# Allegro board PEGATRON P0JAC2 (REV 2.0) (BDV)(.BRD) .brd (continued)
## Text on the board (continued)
User.8: list("[Spacing] SOLDERMASK_BOTTOM" "66.Sym Soldermask to Pad Soldermask" "6.7 MIL [SOLDERMASK_SPACING]" "0 MIL" "6.70 MIL" "DRC ERROR CLASS/SOLDERMASK_BOTTOM" "[ThruPin] Dummy (<uTiL>cId4362<uTiL>.1) (-144.19 4584.63)" "[Shape] Package Geometry/Soldermask_Bottom ((-262.3 4419.29) (-0.49 4677.16))" list(-144.190000 4665.250000) nil)@@@list("bobo_dong" "2014/01/13 20:53:31" nil "S0DCOA89102" "g1t-p0jac.11")@@@list("doris_chen" "2014/01/16 14:59:33" nil "JULIA_YU-PC1" "g1t-p0jac_byt-t.13-chk") | list("[Spacing] SOLDERMASK_BOTTOM" "14.Pad Soldermask to Pad Soldermask" "6.7 MIL [SOLDERMASK_SPACING]" "0 MIL" "6.70 MIL" "DRC ERROR CLASS/SOLDERMASK_BOTTOM" "[SmdPin] MCSI_2_CLK_DP_CON (<uTiL>cId875<uTiL>.3) (130.9 3857.59)" "[SmdPin] MCSI_2_CLK_DP_CON (<uTiL>cId2109<uTiL>.4) (128.93 3855.62)" list(128.930000 3855.620000) nil)@@@list("bobo_dong" "2014/01/13 20:52:34" nil "S0DCOA89102" "g1t-p0jac.11")@@@list("doris_chen" "2014/01/16 14:59:02" nil "JULIA_YU-PC1" "g1t-p0jac_byt-t.13-chk") | list("[Spacing] SOLDERMASK_BOTTOM" "12.Pad Soldermask to Pad Soldermask" "6.7 MIL [SOLDERMASK_SPACING]" "0 MIL" "6.70 MIL" "DRC ERROR CLASS/SOLDERMASK_BOTTOM" "[SmdPin] MCSI_2_CLK_DP (<uTiL>cId875<uTiL>.4) (130.9 3808.37)" "[SmdPin] MCSI_2_CLK_DP (<uTiL>cId2109<uTiL>.3) (128.93 3810.34)" list(128.930000 3810.340000) nil)@@@list("bobo_dong" "2014/01/13 20:52:33" nil "S0DCOA89102" "g1t-p0jac.11")@@@list("doris_chen" "2014/01/16 14:59:01" nil "JULIA_YU-PC1" "g1t-p0jac_byt-t.13-chk") | list("[Spacing] SOLDERMASK_BOTTOM" "13.Pad Soldermask to Pad Soldermask" "6.7 MIL [SOLDERMASK_SPACING]" "0 MIL" "6.70 MIL" "DRC ERROR CLASS/SOLDERMASK_BOTTOM" "[SmdPin] MCSI_2_CLK_DN_CON (<uTiL>cId875<uTiL>.2) (152.56 3857.59)" "[SmdPin] MCSI_2_CLK_DN_CON (<uTiL>cId2109<uTiL>.2) (154.53 3855.62)" list(154.530000 3855.620000) nil)@@@list("bobo_dong" "2014/01/13 20:52:32" nil "S0DCOA89102" "g1t-p0jac.11")@@@list("doris_chen" "2014/01/16 14:59:01" nil "JULIA_YU-PC1" "g1t-p0jac_byt-t.13-chk") | list("[Spacing] SOLDERMASK_BOTTOM" "11.Pad Soldermask to Pad Soldermask" "6.7 MIL [SOLDERMASK_SPACING]" "0 MIL" "6.70 MIL" "DRC ERROR CLASS/SOLDERMASK_BOTTOM" "[SmdPin] MCSI_2_CLK_DN (<uTiL>cId875<uTiL>.1) (152.56 3808.37)" "[SmdPin] MCSI_2_CLK_DN (<uTiL>cId2109<uTiL>.1) (154.53 3810.34)" list(154.530000 3810.340000) nil)@@@list("bobo_dong" "2014/01/13 20:52:31" nil "S0DCOA89102" "g1t-p0jac.11")@@@list("doris_chen" "2014/01/16 14:59:00" nil "JULIA_YU-PC1" "g1t-p0jac_byt-t.13-chk") | list("[Spacing] SOLDERMASK_BOTTOM" "17.Pad Soldermask to Pad Soldermask" "6.7 MIL [SOLDERMASK_SPACING]" "0 MIL" "6.70 MIL" "DRC ERROR CLASS/SOLDERMASK_BOTTOM" "[SmdPin] MCSI_2_DATA_DP_CON (<uTiL>cId876<uTiL>.3) (178.9 3857.59)" "[SmdPin] MCSI_2_DATA_DP_CON (<uTiL>cId2108<uTiL>.4) (176.93 3855.62)" list(176.930000 3855.620000) nil)@@@list("bobo_dong" "2014/01/13 20:52:49" nil "S0DCOA89102" "g1t-p0jac.11")@@@list("doris_chen" "2014/01/16 14:59:04" nil "JULIA_YU-PC1" "g1t-p0jac_byt-t.13-chk") | list("[Spacing] SOLDERMASK_BOTTOM" "16.Pad Soldermask to Pad Soldermask" "6.7 MIL [SOLDERMASK_SPACING]" "0 MIL" "6.70 MIL" "DRC ERROR CLASS/SOLDERMASK_BOTTOM" "[SmdPin] MCSI_2_DATA_DP (<uTiL>cId876<uTiL>.4) (178.9 3808.37)" "[SmdPin] MCSI_2_DATA_DP (<uTiL>cId2108<uTiL>.3) (176.93 3810.34)" list(176.930000 3810.340000) nil)@@@list("bobo_dong" "2014/01/13 20:52:50" nil "S0DCOA89102" "g1t-p0jac.11")@@@list("doris_chen" "2014/01/16 14:59:03" nil "JULIA_YU-PC1" "g1t-p0jac_byt-t.13-chk") | list("[Spacing] SOLDERMASK_BOTTOM" "21.Pad Soldermask to Pad Soldermask" "6.7 MIL [SOLDERMASK_SPACING]" "0 MIL" "6.70 MIL" "DRC ERROR CLASS/SOLDERMASK_BOTTOM" "[SmdPin] MCSI_2_DATA_DN_CON (<uTiL>cId876<uTiL>.2) (200.56 3857.59)" "[SmdPin] MCSI_2_DATA_DN_CON (<uTiL>cId2108<uTiL>.2) (202.53 3855.62)" list(202.530000 3855.620000) nil)@@@list("bobo_dong" "2014/01/13 20:52:47" nil "S0DCOA89102" "g1t-p0jac.11")@@@list("doris_chen" "2014/01/16 14:59:06" nil "JULIA_YU-PC1" "g1t-p0jac_byt-t.13-chk") | list("[Spacing] SOLDERMASK_BOTTOM" "15.Pad Soldermask to Pad Soldermask" "6.7 MIL [SOLDERMASK_SPACING]" "0 MIL" "6.70 MIL" "DRC ERROR CLASS/SOLDERMASK_BOTTOM" "[SmdPin] MCSI_2_DATA_DN (<uTiL>cId876<uTiL>.1) (200.56 3808.37)" "[SmdPin] MCSI_2_DATA_DN (<uTiL>cId2108<uTiL>.1) (202.53 3810.34)" list(202.530000 3810.340000) nil)@@@list("bobo_dong" "2014/01/13 20:52:49" nil "S0DCOA89102" "g1t-p0jac.11")@@@list("doris_chen" "2014/01/16 14:59:03" nil "JULIA_YU-PC1" "g1t-p0jac_byt-t.13-chk") | list("[Spacing] SOLDERMASK_BOTTOM" "23.Pad Soldermask to Pad Soldermask" "6.7 MIL [SOLDERMASK_SPACING]" "0 MIL" "6.70 MIL" "DRC ERROR CLASS/SOLDERMASK_BOTTOM" "[SmdPin] EDP_LVDS_1+_R (<uTiL>cId3904<uTiL>.2) (1818.12 284.81)" "[SmdPin] EDP_LVDS_1+_R (<uTiL>cId3868<uTiL>.2) (1820.09 286.78)" list(1820.090000 286.780000) nil)@@@list("bobo_dong" "2014/01/13 20:52:54" nil "S0DCOA89102" "g1t-p0jac.11")@@@list("doris_chen" "2014/01/16 14:59:07" nil "JULIA_YU-PC1" "g1t-p0jac_byt-t.13-chk") | list("[Spacing] SOLDERMASK_BOTTOM" "24.Pad Soldermask to Pad Soldermask" "6.7 MIL [SOLDERMASK_SPACING]" "0 MIL" "6.70 MIL" "DRC ERROR CLASS/SOLDERMASK_BOTTOM" "[SmdPin] EDP_LVDS_1-_R (<uTiL>cId3904<uTiL>.3) (1818.12 263.15)" "[SmdPin] EDP_LVDS_1-_R (<uTiL>cId3868<uTiL>.4) (1820.09 261.18)" list(1820.090000 261.180000) nil)@@@list("bobo_dong" "2014/01/13 20:52:55" nil "S0DCOA89102" "g1t-p0jac.11")@@@list("doris_chen" "2014/01/16 14:59:07" nil "JULIA_YU-PC1" "g1t-p0jac_byt-t.13-chk") | list("[Spacing] SOLDERMASK_BOTTOM" "27.Pad Soldermask to Pad Soldermask" "6.7 MIL [SOLDERMASK_SPACING]" "0 MIL" "6.70 MIL" "DRC ERROR CLASS/SOLDERMASK_BOTTOM" "[SmdPin] EDP_LVDS_0-_R (<uTiL>cId3906<uTiL>.2) (1818.12 229.81)" "[SmdPin] EDP_LVDS_0-_R (<uTiL>cId3869<uTiL>.2) (1820.09 231.78)" list(1820.090000 231.780000) nil)@@@list("bobo_dong" "2014/01/13 20:53:02" nil "S0DCOA89102" "g1t-p0jac.11")@@@list("doris_chen" "2014/01/16 14:59:09" nil "JULIA_YU-PC1" "g1t-p0jac_byt-t.13-chk") | list("[Spacing] SOLDERMASK_BOTTOM" "28.Pad Soldermask to Pad Soldermask" "6.7 MIL [SOLDERMASK_SPACING]" "0 MIL" "6.70 MIL" "DRC ERROR CLASS/SOLDERMASK_BOTTOM" "[SmdPin] EDP_LVDS_0+_R (<uTiL>cId3906<uTiL>.3) (1818.12 208.15)" "[SmdPin] EDP_LVDS_0+_R (<uTiL>cId3869<uTiL>.4) (1820.09 206.18)" list(1820.090000 206.180000) nil)@@@list("bobo_dong" "2014/01/13 20:53:01" nil "S0DCOA89102" "g1t-p0jac.11")@@@list("doris_chen" "2014/01/16 14:59:10" nil "JULIA_YU-PC1" "g1t-p0jac_byt-t.13-chk") | list("[Spacing] SOLDERMASK_BOTTOM" "31.Pad Soldermask to Pad Soldermask" "6.7 MIL [SOLDERMASK_SPACING]" "0 MIL" "6.70 MIL" "DRC ERROR CLASS/SOLDERMASK_BOTTOM" "[SmdPin] EDP_LVDS_2-_R (<uTiL>cId3903<uTiL>.2) (1818.12 176.81)" "[SmdPin] EDP_LVDS_2-_R (<uTiL>cId3867<uTiL>.2) (1820.09 178.78)" list(1820.090000 178.780000) nil)@@@list("bobo_dong" "2014/01/13 20:53:04" nil "S0DCOA89102" "g1t-p0jac.11")@@@list("doris_chen" "2014/01/16 14:59:11" nil "JULIA_YU-PC1" "g1t-p0jac_byt-t.13-chk") | list("[Spacing] SOLDERMASK_BOTTOM" "33.Pad Soldermask to Pad Soldermask" "6.7 MIL [SOLDERMASK_SPACING]" "0 MIL" "6.70 MIL" "DRC ERROR CLASS/SOLDERMASK_BOTTOM" "[SmdPin] EDP_LVDS_2+_R (<uTiL>cId3903<uTiL>.3) (1818.12 155.15)" "[SmdPin] EDP_LVDS_2+_R (<uTiL>cId3867<uTiL>.4) (1820.09 153.18)" list(1820.090000 153.180000) nil)@@@list("bobo_dong" "2014/01/13 20:53:05" nil "S0DCOA89102" "g1t-p0jac.11")@@@list("doris_chen" "2014/01/16 14:59:13" nil "JULIA_YU-PC1" "g1t-p0jac_byt-t.13-chk") | list("[Spacing] SOLDERMASK_BOTTOM" "34.Pad Soldermask to Pad Soldermask" "6.7 MIL [SOLDERMASK_SPACING]" "0 MIL" "6.70 MIL" "DRC ERROR CLASS/SOLDERMASK_BOTTOM" "[SmdPin] EDP_LVDS_C+_R (<uTiL>cId3905<uTiL>.2) (1818.12 121.81)" "[SmdPin] EDP_LVDS_C+_R (<uTiL>cId3865<uTiL>.2) (1820.09 123.78)" list(1820.090000 123.780000) nil)@@@list("bobo_dong" "2014/01/13 20:53:08" nil "S0DCOA89102" "g1t-p0jac.11")@@@list("doris_chen" "2014/01/16 14:59:13" nil "JULIA_YU-PC1" "g1t-p0jac_byt-t.13-chk") | list("[Spacing] SOLDERMASK_BOTTOM" "35.Pad Soldermask to Pad Soldermask" "6.7 MIL [SOLDERMASK_SPACING]" "0 MIL" "6.70 MIL" "DRC ERROR CLASS/SOLDERMASK_BOTTOM" "[SmdPin] EDP_LVDS_C-_R (<uTiL>cId3905<uTiL>.3) (1818.12 100.15)" "[SmdPin] EDP_LVDS_C-_R (<uTiL>cId3865<uTiL>.4) (1820.09 98.18)" list(1820.090000 98.180000) nil)@@@list("bobo_dong" "2014/01/13 20:53:07" nil "S0DCOA89102" "g1t-p0jac.11")@@@list("doris_chen" "2014/01/16 14:59:14" nil "JULIA_YU-PC1" "g1t-p0jac_byt-t.13-chk") | list("[Spacing] SOLDERMASK_BOTTOM" "39.Pad Soldermask to Pad Soldermask" "6.7 MIL [SOLDERMASK_SPACING]" "0 MIL" "6.70 MIL" "DRC ERROR CLASS/SOLDERMASK_BOTTOM" "[SmdPin] EDP_LVDS_3+_R (<uTiL>cId3902<uTiL>.2) (1819.12 67.81)" "[SmdPin] EDP_LVDS_3+_R (<uTiL>cId3866<uTiL>.2) (1821.09 69.78)" list(1821.090000 69.780000) nil)@@@list("bobo_dong" "2014/01/13 20:53:11" nil "S0DCOA89102" "g1t-p0jac.11")@@@list("doris_chen" "2014/01/16 14:59:16" nil "JULIA_YU-PC1" "g1t-p0jac_byt-t.13-chk") | list("[Spacing] SOLDERMASK_BOTTOM" "40.Pad Soldermask to Pad Soldermask" "6.7 MIL [SOLDERMASK_SPACING]" "0 MIL" "6.70 MIL" "DRC ERROR CLASS/SOLDERMASK_BOTTOM" "[SmdPin] EDP_LVDS_3-_R (<uTiL>cId3902<uTiL>.3) (1819.12 46.15)" "[SmdPin] EDP_LVDS_3-_R (<uTiL>cId3866<uTiL>.4) (1821.09 44.18)" list(1821.090000 44.180000) nil)@@@list("bobo_dong" "2014/01/13 20:53:12" nil "S0DCOA89102" "g1t-p0jac.11")@@@list("doris_chen" "2014/01/16 14:59:16" nil "JULIA_YU-PC1" "g1t-p0jac_byt-t.13-chk") | list("[Spacing] SOLDERMASK_BOTTOM" "26.Pad Soldermask to Pad Soldermask" "6.7 MIL [SOLDERMASK_SPACING]" "0 MIL" "6.70 MIL" "DRC ERROR CLASS/SOLDERMASK_BOTTOM" "[SmdPin] TB0P (<uTiL>cId3904<uTiL>.1) (1867.34 284.81)" "[SmdPin] TB0P (<uTiL>cId3868<uTiL>.1) (1865.37 286.78)" list(1865.370000 286.780000) nil)@@@list("bobo_dong" "2014/01/13 20:52:53" nil "S0DCOA89102" "g1t-p0jac.11")@@@list("doris_chen" "2014/01/16 14:59:08" nil "JULIA_YU-PC1" "g1t-p0jac_byt-t.13-chk") | list("[Spacing] SOLDERMASK_BOTTOM" "25.Pad Soldermask to Pad Soldermask" "6.7 MIL [SOLDERMASK_SPACING]" "0 MIL" "6.70 MIL" "DRC ERROR CLASS/SOLDERMASK_BOTTOM" "[SmdPin] TB0N (<uTiL>cId3904<uTiL>.4) (1867.34 263.15)" "[SmdPin] TB0N (<uTiL>cId3868<uTiL>.3) (1865.37 261.18)" list(1865.370000 261.180000) nil)@@@list("bobo_dong" "2014/01/13 20:52:54" nil "S0DCOA89102" "g1t-p0jac.11")@@@list("doris_chen" "2014/01/16 14:59:07" nil "JULIA_YU-PC1" "g1t-p0jac_byt-t.13-chk") | list("[Spacing] SOLDERMASK_BOTTOM" "29.Pad Soldermask to Pad Soldermask" "6.7 MIL [SOLDERMASK_SPACING]" "0 MIL" "6.70 MIL" "DRC ERROR CLASS/SOLDERMASK_BOTTOM" "[SmdPin] TA0N (<uTiL>cId3906<uTiL>.1) (1867.34 229.81)" "[SmdPin] TA0N (<uTiL>cId3869<uTiL>.1) (1865.37 231.78)" list(1865.370000 231.780000) nil)@@@list("bobo_dong" "2014/01/13 20:52:55" nil "S0DCOA89102" "g1t-p0jac.11")@@@list("doris_chen" "2014/01/16 14:59:10" nil "JULIA_YU-PC1" "g1t-p0jac_byt-t.13-chk") | list("[Spacing] SOLDERMASK_BOTTOM" "30.Pad Soldermask to Pad Soldermask" "6.7 MIL [SOLDERMASK_SPACING]" "0 MIL" "6.70 MIL" "DRC ERROR CLASS/SOLDERMASK_BOTTOM" "[SmdPin] TA0P (<uTiL>cId3906<uTiL>.4) (1867.34 208.15)" "[SmdPin] TA0P (<uTiL>cId3869<uTiL>.3) (1865.37 206.18)" list(1865.370000 206.180000) nil)@@@list("bobo_dong" "2014/01/13 20:53:00" nil "S0DCOA89102" "g1t-p0jac.11")@@@list("doris_chen" "2014/01/16 14:59:11" nil "JULIA_YU-PC1" "g1t-p0jac_byt-t.13-chk") | list("[Spacing] SOLDERMASK_BOTTOM" "32.Pad Soldermask to Pad Soldermask" "6.7 MIL [SOLDERMASK_SPACING]" "0 MIL" "6.70 MIL" "DRC ERROR CLASS/SOLDERMASK_BOTTOM" "[SmdPin] TC0N (<uTiL>cId3903<uTiL>.1) (1867.34 176.81)" "[SmdPin] TC0N (<uTiL>cId3867<uTiL>.1) (1865.37 178.78)" list(1865.370000 178.780000) nil)@@@list("bobo_dong" "2014/01/13 20:53:03" nil "S0DCOA89102" "g1t-p0jac.11")@@@list("doris_chen" "2014/01/16 14:59:12" nil "JULIA_YU-PC1" "g1t-p0jac_byt-t.13-chk") | list("[Spacing] SOLDERMASK_BOTTOM" "38.Pad Soldermask to Pad Soldermask" "6.7 MIL [SOLDERMASK_SPACING]" "0 MIL" "6.70 MIL" "DRC ERROR CLASS/SOLDERMASK_BOTTOM" "[SmdPin] TC0P (<uTiL>cId3903<uTiL>.4) (1867.34 155.15)" "[SmdPin] TC0P (<uTiL>cId3867<uTiL>.3) (1865.37 153.18)" list(1865.370000 153.180000) nil)@@@list("bobo_dong" "2014/01/13 20:53:03" nil "S0DCOA89102" "g1t-p0jac.11")@@@list("doris_chen" "2014/01/16 14:59:15" nil "JULIA_YU-PC1" "g1t-p0jac_byt-t.13-chk") | list("[Spacing] SOLDERMASK_BOTTOM" "36.Pad Soldermask to Pad Soldermask" "6.7 MIL [SOLDERMASK_SPACING]" "0 MIL" "6.70 MIL" "DRC ERROR CLASS/SOLDERMASK_BOTTOM" "[SmdPin] TCK0P (<uTiL>cId3905<uTiL>.1) (1867.34 121.81)" "[SmdPin] TCK0P (<uTiL>cId3865<uTiL>.1) (1865.37 123.78)" list(1865.370000 123.780000) nil)@@@list("bobo_dong" "2014/01/13 20:53:06" nil "S0DCOA89102" "g1t-p0jac.11")@@@list("doris_chen" "2014/01/16 14:59:14" nil "JULIA_YU-PC1" "g1t-p0jac_byt-t.13-chk") | list("[Spacing] SOLDERMASK_BOTTOM" "37.Pad Soldermask to Pad Soldermask" "6.7 MIL [SOLDERMASK_SPACING]" "0 MIL" "6.70 MIL" "DRC ERROR CLASS/SOLDERMASK_BOTTOM" "[SmdPin] TCK0N (<uTiL>cId3905<uTiL>.4) (1867.34 100.15)" "[SmdPin] TCK0N (<uTiL>cId3865<uTiL>.3) (1865.37 98.18)" list(1865.370000 98.180000) nil)@@@list("bobo_dong" "2014/01/13 20:53:07" nil "S0DCOA89102" "g1t-p0jac.11")@@@list("doris_chen" "2014/01/16 14:59:15" nil "JULIA_YU-PC1" "g1t-p0jac_byt-t.13-chk") | list("[Spacing] SOLDERMASK_BOTTOM" "41.Pad Soldermask to Pad Soldermask" "6.7 MIL [SOLDERMASK_SPACING]" "0 MIL" "6.70 MIL" "DRC ERROR CLASS/SOLDERMASK_BOTTOM" "[SmdPin] TD0P (<uTiL>cId3902<uTiL>.1) (1868.34 67.81)" "[SmdPin] TD0P (<uTiL>cId3866<uTiL>.1) (1866.37 69.78)" list(1866.370000 69.780000) nil)@@@list("bobo_dong" "2014/01/13 20:53:09" nil "S0DCOA89102" "g1t-p0jac.11")@@@list("doris_chen" "2014/01/16 14:59:17" nil "JULIA_YU-PC1" "g1t-p0jac_byt-t.13-chk") | list("[Spacing] SOLDERMASK_BOTTOM" "45.Pad Soldermask to Pad Soldermask" "6.7 MIL [SOLDERMASK_SPACING]" "0 MIL" "6.70 MIL" "DRC ERROR CLASS/SOLDERMASK_BOTTOM" "[SmdPin] TD0N (<uTiL>cId3902<uTiL>.4) (1868.34 46.15)" "[SmdPin] TD0N (<uTiL>cId3866<uTiL>.3) (1866.37 44.18)" list(1866.370000 44.180000) nil)@@@list("bobo_dong" "2014/01/13 20:53:10" nil "S0DCOA89102" "g1t-p0jac.11")@@@list("doris_chen" "2014/01/16 14:59:19" nil "JULIA_YU-PC1" "g1t-p0jac_byt-t.13-chk") | list("[Spacing] SOLDERMASK_BOTTOM" "20.Pad Soldermask to Pad Soldermask" "6.7 MIL [SOLDERMASK_SPACING]" "0 MIL" "6.70 MIL" "DRC ERROR CLASS/SOLDERMASK_BOTTOM" "[SmdPin] USB2_DP (<uTiL>cId3907<uTiL>.2) (2736.12 2264.81)" "[SmdPin] USB2_DP (<uTiL>cId3864<uTiL>.3) (2738.09 2266.78)" list(2738.090000 2266.780000) nil)@@@list("bobo_dong" "2014/01/13 20:52:52" nil "S0DCOA89102" "g1t-p0jac.11")@@@list("doris_chen" "2014/01/16 14:59:05" nil "JULIA_YU-PC1" "g1t-p0jac_byt-t.13-chk") | list("[Spacing] SOLDERMASK_BOTTOM" "18.Pad Soldermask to Pad Soldermask" "6.7 MIL [SOLDERMASK_SPACING]" "0 MIL" "6.70 MIL" "DRC ERROR CLASS/SOLDERMASK_BOTTOM" "[SmdPin] USB2_DN (<uTiL>cId3907<uTiL>.3) (2736.12 2243.15)" "[SmdPin] USB2_DN (<uTiL>cId3864<uTiL>.1) (2738.09 2241.18)" list(2738.090000 2241.180000) nil)@@@list("bobo_dong" "2014/01/13 20:52:51" nil "S0DCOA89102" "g1t-p0jac.11")@@@list("doris_chen" "2014/01/16 14:59:04" nil "JULIA_YU-PC1" "g1t-p0jac_byt-t.13-chk") | list("[Spacing] SOLDERMASK_BOTTOM" "42.Pad Soldermask to Pad Soldermask" "6.7 MIL [SOLDERMASK_SPACING]" "0 MIL" "6.70 MIL" "DRC ERROR CLASS/SOLDERMASK_BOTTOM" "[SmdPin] DDI0_TX1_DN_R (<uTiL>cId2167<uTiL>.4) (2737.82 1841.88)" "[SmdPin] DDI0_TX1_DN_R (<uTiL>cId2112<uTiL>.3) (2739.79 1843.85)" list(2739.790000 1843.850000) nil)@@@list("bobo_dong" "2014/01/13 20:53:14" nil "S0DCOA89102" "g1t-p0jac.11")@@@list("doris_chen" "2014/01/16 14:59:18" nil "JULIA_YU-PC1" "g1t-p0jac_byt-t.13-chk") | list("[Spacing] SOLDERMASK_BOTTOM" "43.Pad Soldermask to Pad Soldermask" "6.7 MIL [SOLDERMASK_SPACING]" "0 MIL" "6.70 MIL" "DRC ERROR CLASS/SOLDERMASK_BOTTOM" "[SmdPin] DDI0_TX1_DP_R (<uTiL>cId2167<uTiL>.1) (2737.82 1820.22)" "[SmdPin] DDI0_TX1_DP_R (<uTiL>cId2112<uTiL>.1) (2739.79 1818.25)" list(2739.790000 1818.250000) nil)@@@list("bobo_dong" "2014/01/13 20:53:12" nil "S0DCOA89102" "g1t-p0jac.11")@@@list("doris_chen" "2014/01/16 14:59:18" nil "JULIA_YU-PC1" "g1t-p0jac_byt-t.13-chk") | list("[Spacing] SOLDERMASK_BOTTOM" "50.Pad Soldermask to Pad Soldermask" "6.7 MIL [SOLDERMASK_SPACING]" "0 MIL" "6.70 MIL" "DRC ERROR CLASS/SOLDERMASK_BOTTOM" "[SmdPin] DDI0_TX0_DN_R (<uTiL>cId2168<uTiL>.4) (2737.82 1721.88)" "[SmdPin] DDI0_TX0_DN_R (<uTiL>cId2113<uTiL>.3) (2739.79 1723.85)" list(2739.790000 1723.850000) nil)@@@list("bobo_dong" "2014/01/13 20:53:17" nil "S0DCOA89102" "g1t-p0jac.11")@@@list("doris_chen" "2014/01/16 14:59:22" nil "JULIA_YU-PC1" "g1t-p0jac_byt-t.13-chk") | list("[Spacing] SOLDERMASK_BOTTOM" "47.Pad Soldermask to Pad Soldermask" "6.7 MIL [SOLDERMASK_SPACING]" "0 MIL" "6.70 MIL" "DRC ERROR CLASS/SOLDERMASK_BOTTOM" "[SmdPin] DDI0_TX0_DP_R (<uTiL>cId2168<uTiL>.1) (2737.82 1700.22)" "[SmdPin] DDI0_TX0_DP_R (<uTiL>cId2113<uTiL>.1) (2739.79 1698.25)" list(2739.790000 1698.250000) nil)@@@list("bobo_dong" "2014/01/13 20:53:15" nil "S0DCOA89102" "g1t-p0jac.11")@@@list("doris_chen" "2014/01/16 14:59:20" nil "JULIA_YU-PC1" "g1t-p0jac_byt-t.13-chk") | list("[Spacing] SOLDERMASK_BOTTOM" "53.Pad Soldermask to Pad Soldermask" "6.7 MIL [SOLDERMASK_SPACING]" "0 MIL" "6.70 MIL" "DRC ERROR CLASS/SOLDERMASK_BOTTOM" "[SmdPin] DDI0_TX2_DN_R (<uTiL>cId2166<uTiL>.4) (2737.82 1597.88)" "[SmdPin] DDI0_TX2_DN_R (<uTiL>cId2111<uTiL>.3) (2739.79 1599.85)" list(2739.790000 1599.850000) nil)@@@list("bobo_dong" "2014/01/13 20:53:19" nil "S0DCOA89102" "g1t-p0jac.11")@@@list("doris_chen" "2014/01/16 14:59:25" nil "JULIA_YU-PC1" "g1t-p0jac_byt-t.13-chk") | list("[Spacing] SOLDERMASK_BOTTOM" "52.Pad Soldermask to Pad Soldermask" "6.7 MIL [SOLDERMASK_SPACING]" "0 MIL" "6.70 MIL" "DRC ERROR CLASS/SOLDERMASK_BOTTOM" "[SmdPin] DDI0_TX2_DP_R (<uTiL>cId2166<uTiL>.1) (2737.82 1576.22)" "[SmdPin] DDI0_TX2_DP_R (<uTiL>cId2111<uTiL>.1) (2739.79 1574.25)" list(2739.790000 1574.250000) nil)@@@list("bobo_dong" "2014/01/13 20:53:18" nil "S0DCOA89102" "g1t-p0jac.11")@@@list("doris_chen" "2014/01/16 14:59:23" nil "JULIA_YU-PC1" "g1t-p0jac_byt-t.13-chk") | list("[Spacing] SOLDERMASK_BOTTOM" "57.Pad Soldermask to Pad Soldermask" "6.7 MIL [SOLDERMASK_SPACING]" "0 MIL" "6.70 MIL" "DRC ERROR CLASS/SOLDERMASK_BOTTOM" "[SmdPin] DDI0_TX3_DN_R (<uTiL>cId2165<uTiL>.4) (2737.82 1475.88)" "[SmdPin] DDI0_TX3_DN_R (<uTiL>cId2110<uTiL>.3) (2739.79 1477.85)" list(2739.790000 1477.850000) nil)@@@list("bobo_dong" "2014/01/13 20:53:22" nil "S0DCOA89102" "g1t-p0jac.11")@@@list("doris_chen" "2014/01/16 14:59:27" nil "JULIA_YU-PC1" "g1t-p0jac_byt-t.13-chk") | list("[Spacing] SOLDERMASK_BOTTOM" "56.Pad Soldermask to Pad Soldermask" "6.7 MIL [SOLDERMASK_SPACING]" "0 MIL" "6.70 MIL" "DRC ERROR CLASS/SOLDERMASK_BOTTOM" "[SmdPin] DDI0_TX3_DP_R (<uTiL>cId2165<uTiL>.1) (2737.82 1454.22)" "[SmdPin] DDI0_TX3_DP_R (<uTiL>cId2110<uTiL>.1) (2739.79 1452.25)" list(2739.790000 1452.250000) nil)@@@list("bobo_dong" "2014/01/13 20:53:21" nil "S0DCOA89102" "g1t-p0jac.11")@@@list("doris_chen" "2014/01/16 14:59:26" nil "JULIA_YU-PC1" "g1t-p0jac_byt-t.13-chk") | list("[Spacing] SOLDERMASK_BOTTOM" "22.Pad Soldermask to Pad Soldermask" "6.7 MIL [SOLDERMASK_SPACING]" "0 MIL" "6.70 MIL" "DRC ERROR CLASS/SOLDERMASK_BOTTOM" "[SmdPin] 85_USB2_CPU_P1_DP_C (<uTiL>cId3907<uTiL>.1) (2785.34 2264.81)" "[SmdPin] 85_USB2_CPU_P1_DP_C (<uTiL>cId3864<uTiL>.4) (2783.37 2266.78)" list(2783.370000 2266.780000) nil)@@@list("bobo_dong" "2014/01/13 20:52:52" nil "S0DCOA89102" "g1t-p0jac.11")@@@list("doris_chen" "2014/01/16 14:59:06" nil "JULIA_YU-PC1" "g1t-p0jac_byt-t.13-chk") | list("[Spacing] SOLDERMASK_BOTTOM" "19.Pad Soldermask to Pad Soldermask" "6.7 MIL [SOLDERMASK_SPACING]" "0 MIL" "6.70 MIL" "DRC ERROR CLASS/SOLDERMASK_BOTTOM" "[SmdPin] 85_USB2_CPU_P1_DN_C (<uTiL>cId3907<uTiL>.4) (2785.34 2243.15)" "[SmdPin] 85_USB2_CPU_P1_DN_C (<uTiL>cId3864<uTiL>.2) (2783.37 2241.18)" list(2783.370000 2241.180000) nil)@@@list("bobo_dong" "2014/01/13 20:52:51" nil "S0DCOA89102" "g1t-p0jac.11")@@@list("doris_chen" "2014/01/16 14:59:05" nil "JULIA_YU-PC1" "g1t-p0jac_byt-t.13-chk") | list("[Spacing] SOLDERMASK_BOTTOM" "46.Pad Soldermask to Pad Soldermask" "6.7 MIL [SOLDERMASK_SPACING]" "0 MIL" "6.70 MIL" "DRC ERROR CLASS/SOLDERMASK_BOTTOM" "[SmdPin] HDMI_DATA1_DN_CON (<uTiL>cId2167<uTiL>.3) (2787.04 1841.88)" "[SmdPin] HDMI_DATA1_DN_CON (<uTiL>cId2112<uTiL>.4) (2785.07 1843.85)" list(2785.070000 1843.850000) nil)@@@list("bobo_dong" "2014/01/13 20:53:15" nil "S0DCOA89102" "g1t-p0jac.11")@@@list("doris_chen" "2014/01/16 14:59:20" nil "JULIA_YU-PC1" "g1t-p0jac_byt-t.13-chk") | list("[Spacing] SOLDERMASK_BOTTOM" "44.Pad Soldermask to Pad Soldermask" "6.7 MIL [SOLDERMASK_SPACING]" "0 MIL" "6.70 MIL" "DRC ERROR CLASS/SOLDERMASK_BOTTOM" "[SmdPin] HDMI_DATA1_DP_CON (<uTiL>cId2167<uTiL>.2) (2787.04 1820.22)" "[SmdPin] HDMI_DATA1_DP_CON (<uTiL>cId2112<uTiL>.2) (2785.07 1818.25)" list(2785.070000 1818.250000) nil)@@@list("bobo_dong" "2014/01/13 20:53:13" nil "S0DCOA89102" "g1t-p0jac.11")@@@list("doris_chen" "2014/01/16 14:59:19" nil "JULIA_YU-PC1" "g1t-p0jac_byt-t.13-chk") | list("[Spacing] SOLDERMASK_BOTTOM" "49.Pad Soldermask to Pad Soldermask" "6.7 MIL [SOLDERMASK_SPACING]" "0 MIL" "6.70 MIL" "DRC ERROR CLASS/SOLDERMASK_BOTTOM" "[SmdPin] HDMI_DATA2_DN_CON (<uTiL>cId2168<uTiL>.3) (2787.04 1721.88)" "[SmdPin] HDMI_DATA2_DN_CON (<uTiL>cId2113<uTiL>.4) (2785.07 1723.85)" list(2785.070000 1723.850000) nil)@@@list("bobo_dong" "2014/01/13 20:53:17" nil "S0DCOA89102" "g1t-p0jac.11")@@@list("doris_chen" "2014/01/16 14:59:22" nil "JULIA_YU-PC1" "g1t-p0jac_byt-t.13-chk") | list("[Spacing] SOLDERMASK_BOTTOM" "48.Pad Soldermask to Pad Soldermask" "6.7 MIL [SOLDERMASK_SPACING]" "0 MIL" "6.70 MIL" "DRC ERROR CLASS/SOLDERMASK_BOTTOM" "[SmdPin] HDMI_DATA2_DP_CON (<uTiL>cId2168<uTiL>.2) (2787.04 1700.22)" "[SmdPin] HDMI_DATA2_DP_CON (<uTiL>cId2113<uTiL>.2) (2785.07 1698.25)" list(2785.070000 1698.250000) nil)@@@list("bobo_dong" "2014/01/13 20:53:16" nil "S0DCOA89102" "g1t-p0jac.11")@@@list("doris_chen" "2014/01/16 14:59:21" nil "JULIA_YU-PC1" "g1t-p0jac_byt-t.13-chk") | list("[Spacing] SOLDERMASK_BOTTOM" "54.Pad Soldermask to Pad Soldermask" "6.7 MIL [SOLDERMASK_SPACING]" "0 MIL" "6.70 MIL" "DRC ERROR CLASS/SOLDERMASK_BOTTOM" "[SmdPin] HDMI_DATA0_DN_CON (<uTiL>cId2166<uTiL>.3) (2787.04 1597.88)" "[SmdPin] HDMI_DATA0_DN_CON (<uTiL>cId2111<uTiL>.4) (2785.07 1599.85)" list(2785.070000 1599.850000) nil)@@@list("bobo_dong" "2014/01/13 20:53:20" nil "S0DCOA89102" "g1t-p0jac.11")@@@list("doris_chen" "2014/01/16 14:59:25" nil "JULIA_YU-PC1" "g1t-p0jac_byt-t.13-chk") | list("[Spacing] SOLDERMASK_BOTTOM" "51.Pad Soldermask to Pad Soldermask" "6.7 MIL [SOLDERMASK_SPACING]" "0 MIL" "6.70 MIL" "DRC ERROR CLASS/SOLDERMASK_BOTTOM" "[SmdPin] HDMI_DATA0_DP_CON (<uTiL>cId2166<uTiL>.2) (2787.04 1576.22)" "[SmdPin] HDMI_DATA0_DP_CON (<uTiL>cId2111<uTiL>.2) (2785.07 1574.25)" list(2785.070000 1574.250000) nil)@@@list("bobo_dong" "2014/01/13 20:53:19" nil "S0DCOA89102" "g1t-p0jac.11")@@@list("doris_chen" "2014/01/16 14:59:23" nil "JULIA_YU-PC1" "g1t-p0jac_byt-t.13-chk") | list("[Spacing] SOLDERMASK_BOTTOM" "58.Pad Soldermask to Pad Soldermask" "6.7 MIL [SOLDERMASK_SPACING]" "0 MIL" "6.70 MIL" "DRC ERROR CLASS/SOLDERMASK_BOTTOM" "[SmdPin] HDMI_CLK_DN_CON (<uTiL>cId2165<uTiL>.3) (2787.04 1475.88)" "[SmdPin] HDMI_CLK_DN_CON (<uTiL>cId2110<uTiL>.4) (2785.07 1477.85)" list(2785.070000 1477.850000) nil)@@@list("bobo_dong" "2014/01/13 20:53:23" nil "S0DCOA89102" "g1t-p0jac.11")@@@list("doris_chen" "2014/01/16 14:59:27" nil "JULIA_YU-PC1" "g1t-p0jac_byt-t.13-chk") | list("[Spacing] SOLDERMASK_BOTTOM" "55.Pad Soldermask to Pad Soldermask" "6.7 MIL [SOLDERMASK_SPACING]" "0 MIL" "6.70 MIL" "DRC ERROR CLASS/SOLDERMASK_BOTTOM" "[SmdPin] HDMI_CLK_DP_CON (<uTiL>cId2165<uTiL>.2) (2787.04 1454.22)" "[SmdPin] HDMI_CLK_DP_CON (<uTiL>cId2110<uTiL>.2) (2785.07 1452.25)" list(2785.070000 1452.250000) nil)@@@list("bobo_dong" "2014/01/13 20:53:21" nil "S0DCOA89102" "g1t-p0jac.11")@@@list("doris_chen" "2014/01/16 14:59:26" nil "JULIA_YU-PC1" "g1t-p0jac_byt-t.13-chk") | list("[Spacing] SOLDERMASK_BOTTOM" "62.Pad Soldermask to Pad Soldermask" "6.7 MIL [SOLDERMASK_SPACING]" "6.5 MIL" "0.20 MIL" "DRC ERROR CLASS/SOLDERMASK_BOTTOM" "[ThruPin] HDMI_CLK_DP_CON (<uTiL>cId2273<uTiL>.12) (2998.02 1529.13)" "[ThruPin] HDMI_DATA1_DN_CON (<uTiL>cId2273<uTiL>.8) (2998.02 1560.63)" list(2998.020000 1560.630000) nil)@@@list("bobo_dong" "2014/01/13 20:53:30" nil "S0DCOA89102" "g1t-p0jac.11")@@@list("doris_chen" "2014/01/16 14:59:30" nil "JULIA_YU-PC1" "g1t-p0jac_byt-t.13-chk") | list("[Spacing] SOLDERMASK_BOTTOM" "63.Pad Soldermask to Pad Soldermask" "6.7 MIL [SOLDERMASK_SPACING]" "6.49 MIL" "0.21 MIL" "DRC ERROR CLASS/SOLDERMASK_BOTTOM" "[ThruPin] GND (<uTiL>cId2273<uTiL>.4) (2998.02 1592.12)" "[ThruPin] HDMI_DATA1_DN_CON (<uTiL>cId2273<uTiL>.8) (2998.02 1560.63)" list(2998.020000 1560.630000) nil)@@@list("bobo_dong" "2014/01/13 20:53:28" nil "S0DCOA89102" "g1t-p0jac.11")@@@list("doris_chen" "2014/01/16 14:59:30" nil "JULIA_YU-PC1" "g1t-p0jac_byt-t.13-chk") | list("[Spacing] SOLDERMASK_BOTTOM" "59.Pad Soldermask to Pad Soldermask" "6.7 MIL [SOLDERMASK_SPACING]" "6.49 MIL" "0.21 MIL" "DRC ERROR CLASS/SOLDERMASK_BOTTOM" "[ThruPin] HDMI_CLK_DP_CON (<uTiL>cId2273<uTiL>.12) (2998.02 1529.13)" "[ThruPin] GND (<uTiL>cId2273<uTiL>.16) (2998.02 1497.64)" list(2998.020000 1497.640000) nil)@@@list("bobo_dong" "2014/01/13 20:53:24" nil "S0DCOA89102" "g1t-p0jac.11")@@@list("doris_chen" "2014/01/16 14:59:28" nil "JULIA_YU-PC1" "g1t-p0jac_byt-t.13-chk") | list("[Spacing] SOLDERMASK_BOTTOM" "64.Pad Soldermask to Pad Soldermask" "6.7 MIL [SOLDERMASK_SPACING]" "6.5 MIL" "0.20 MIL" "DRC ERROR CLASS/SOLDERMASK_BOTTOM" "[ThruPin] GND (<uTiL>cId2273<uTiL>.10) (3061.01 1544.88)" "[ThruPin] HDMI_DATA1_DP_CON (<uTiL>cId2273<uTiL>.6) (3061.01 1576.38)" list(3061.010000 1576.380000) nil)@@@list("bobo_dong" "2014/01/13 20:53:28" nil "S0DCOA89102" "g1t-p0jac.11")@@@list("doris_chen" "2014/01/16 14:59:31" nil "JULIA_YU-PC1" "g1t-p0jac_byt-t.13-chk") | list("[Spacing] SOLDERMASK_BOTTOM" "65.Pad Soldermask to Pad Soldermask" "6.7 MIL [SOLDERMASK_SPACING]" "6.49 MIL" "0.21 MIL" "DRC ERROR CLASS/SOLDERMASK_BOTTOM" "[ThruPin] Dummy (<uTiL>cId2273<uTiL>.2) (3061.01 1607.87)" "[ThruPin] HDMI_DATA1_DP_CON (<uTiL>cId2273<uTiL>.6) (3061.01 1576.38)" list(3061.010000 1576.380000) nil)@@@list("bobo_dong" "2014/01/13 20:53:26" nil "S0DCOA89102" "g1t-p0jac.11")@@@list("doris_chen" "2014/01/16 14:59:32" nil "JULIA_YU-PC1" "g1t-p0jac_byt-t.13-chk") | list("[Spacing] SOLDERMASK_BOTTOM" "60.Pad Soldermask to Pad Soldermask" "6.7 MIL [SOLDERMASK_SPACING]" "6.5 MIL" "0.20 MIL" "DRC ERROR CLASS/SOLDERMASK_BOTTOM" "[ThruPin] GND (<uTiL>cId2273<uTiL>.10) (3061.01 1544.88)" "[ThruPin] HDMI_CLK_DN_CON (<uTiL>cId2273<uTiL>.14) (3061.01 1513.38)" list(3061.010000 1513.380000) nil)@@@list("bobo_dong" "2014/01/13 20:53:23" nil "S0DCOA89102" "g1t-p0jac.11")@@@list("doris_chen" "2014/01/16 14:59:28" nil "JULIA_YU-PC1" "g1t-p0jac_byt-t.13-chk") | list("[Spacing] SOLDERMASK_BOTTOM" "61.Pad Soldermask to Pad Soldermask" "6.7 MIL [SOLDERMASK_SPACING]" "6.49 MIL" "0.21 MIL" "DRC ERROR CLASS/SOLDERMASK_BOTTOM" "[ThruPin] HDMI_CLK_DN_CON (<uTiL>cId2273<uTiL>.14) (3061.01 1513.38)" "[ThruPin] HDMI_DDC_SDA_CONN (<uTiL>cId2273<uTiL>.18) (3061.01 1481.89)" list(3061.010000 1481.890000) nil)@@@list("bobo_dong" "2014/01/13 20:53:26" nil "S0DCOA89102" "g1t-p0jac.11")@@@list("doris_chen" "2014/01/16 14:59:29" nil "JULIA_YU-PC1" "g1t-p0jac_byt-t.13-chk") | list("[Spacing] SOLDERMASK_BOTTOM" "67.Sym Soldermask to Pad Soldermask" "6.7 MIL [SOLDERMASK_SPACING]" "0 MIL" "6.70 MIL" "DRC ERROR CLASS/SOLDERMASK_BOTTOM" "[ThruPin] Dummy (<uTiL>cId4361<uTiL>.1) (3045.18 4149.6)" "[Shape] Package Geometry/Soldermask_Bottom ((2887.65 4005.82) (3163.24 4282.59))" list(3151.380000 4149.600000) nil)@@@list("bobo_dong" "2014/01/13 20:53:32" nil "S0DCOA89102" "g1t-p0jac.11")@@@list("doris_chen" "2014/01/16 14:59:33" nil "JULIA_YU-PC1" "g1t-p0jac_byt-t.13-chk") | list("[Spacing] SOLDERMASK_BOTTOM" "33.Pad Soldermask to Pad Soldermask" "6.7 MIL [SOLDERMASK_SPACING]" "0 MIL" "6.70 MIL" "DRC ERROR CLASS/SOLDERMASK_BOTTOM" "[SmdPin] 85_MDSI_C_DP_3 (<uTiL>cId1668<uTiL>.2) (-2189.61 1165.83)" "[SmdPin] 85_MDSI_C_DP_3 (<uTiL>cId1635<uTiL>.2) (-2187.64 1167.8)" list(-2187.640000 1167.800000) nil)@@@list("sky_zheng" "2013/09/13 10:58:31" nil "RDD_704_PC" "g1t-oxygen.10")@@@list("andy_lien" "2013/09/13 12:16:01" nil "ANDY_LIEN-PC" "g1t-oxygen.10") | list("[Spacing] SOLDERMASK_BOTTOM" "35.Pad Soldermask to Pad Soldermask" "6.7 MIL [SOLDERMASK_SPACING]" "0 MIL" "6.70 MIL" "DRC ERROR CLASS/SOLDERMASK_BOTTOM" "[SmdPin] 85_MDSI_C_DN_3 (<uTiL>cId1668<uTiL>.3) (-2189.61 1144.17)" "[SmdPin] 85_MDSI_C_DN_3 (<uTiL>cId1635<uTiL>.4) (-2187.64 1142.2)" list(-2187.640000 1142.200000) nil)@@@list("sky_zheng" "2013/09/13 10:58:32" nil "RDD_704_PC" "g1t-oxygen.10")@@@list("andy_lien" "2013/09/13 12:16:02" nil "ANDY_LIEN-PC" "g1t-oxygen.10") | list("[Spacing] SOLDERMASK_BOTTOM" "37.Pad Soldermask to Pad Soldermask" "6.7 MIL [SOLDERMASK_SPACING]" "0 MIL" "6.70 MIL" "DRC ERROR CLASS/SOLDERMASK_BOTTOM" "[SmdPin] 85_MDSI_C_DP_2 (<uTiL>cId1669<uTiL>.2) (-2189.61 1115.83)" "[SmdPin] 85_MDSI_C_DP_2 (<uTiL>cId1636<uTiL>.2) (-2187.64 1117.8)" list(-2187.640000 1117.800000) nil)@@@list("sky_zheng" "2013/09/13 10:58:36" nil "RDD_704_PC" "g1t-oxygen.10")@@@list("andy_lien" "2013/09/13 12:16:05" nil "ANDY_LIEN-PC" "g1t-oxygen.10") | list("[Spacing] SOLDERMASK_BOTTOM" "39.Pad Soldermask to Pad Soldermask" "6.7 MIL [SOLDERMASK_SPACING]" "0 MIL" "6.70 MIL" "DRC ERROR CLASS/SOLDERMASK_BOTTOM" "[SmdPin] 85_MDSI_C_DN_2 (<uTiL>cId1669<uTiL>.3) (-2189.61 1094.17)" "[SmdPin] 85_MDSI_C_DN_2 (<uTiL>cId1636<uTiL>.4) (-2187.64 1092.2)" list(-2187.640000 1092.200000) nil)@@@list("sky_zheng" "2013/09/13 10:58:37" nil "RDD_704_PC" "g1t-oxygen.10")@@@list("andy_lien" "2013/09/13 12:16:05" nil "ANDY_LIEN-PC" "g1t-oxygen.10") | list("[Spacing] SOLDERMASK_BOTTOM" "29.Pad Soldermask to Pad Soldermask" "6.7 MIL [SOLDERMASK_SPACING]" "0 MIL" "6.70 MIL" "DRC ERROR CLASS/SOLDERMASK_BOTTOM" "[SmdPin] 85_MDSI_C_CLK_DP (<uTiL>cId827<uTiL>.2) (-2189.61 1065.83)" "[SmdPin] 85_MDSI_C_CLK_DP (<uTiL>cId231<uTiL>.2) (-2187.64 1067.8)" list(-2187.640000 1067.800000) nil)@@@list("sky_zheng" "2013/09/13 10:58:27" nil "RDD_704_PC" "g1t-oxygen.10")@@@list("andy_lien" "2013/09/13 12:16:00" nil "ANDY_LIEN-PC" "g1t-oxygen.10") | list("[Spacing] SOLDERMASK_BOTTOM" "31.Pad Soldermask to Pad Soldermask" "6.7 MIL [SOLDERMASK_SPACING]" "0 MIL" "6.70 MIL" "DRC ERROR CLASS/SOLDERMASK_BOTTOM" "[SmdPin] 85_MDSI_C_CLK_DN (<uTiL>cId827<uTiL>.3) (-2189.61 1044.17)" "[SmdPin] 85_MDSI_C_CLK_DN (<uTiL>cId231<uTiL>.4) (-2187.64 1042.2)" list(-2187.640000 1042.200000) nil)@@@list("sky_zheng" "2013/09/13 10:58:28" nil "RDD_704_PC" "g1t-oxygen.10")@@@list("andy_lien" "2013/09/13 12:16:01" nil "ANDY_LIEN-PC" "g1t-oxygen.10") | list("[Spacing] SOLDERMASK_BOTTOM" "23.Pad Soldermask to Pad Soldermask" "6.7 MIL [SOLDERMASK_SPACING]" "0 MIL" "6.70 MIL" "DRC ERROR CLASS/SOLDERMASK_BOTTOM" "[SmdPin] 85_MDSI_C_DP_1 (<uTiL>cId825<uTiL>.2) (-2189.61 1015.83)" "[SmdPin] 85_MDSI_C_DP_1 (<uTiL>cId229<uTiL>.2) (-2187.64 1017.8)" list(-2187.640000 1017.800000) nil)@@@list("sky_zheng" "2013/09/13 10:58:16" nil "RDD_704_PC" "g1t-oxygen.10")@@@list("andy_lien" "2013/09/13 12:15:58" nil "ANDY_LIEN-PC" "g1t-oxygen.10") | list("[Spacing] SOLDERMASK_BOTTOM" "21.Pad Soldermask to Pad Soldermask" "6.7 MIL [SOLDERMASK_SPACING]" "0 MIL" "6.70 MIL" "DRC ERROR CLASS/SOLDERMASK_BOTTOM" "[SmdPin] 85_MDSI_C_DN_1 (<uTiL>cId825<uTiL>.3) (-2189.61 994.17)" "[SmdPin] 85_MDSI_C_DN_1 (<uTiL>cId229<uTiL>.4) (-2187.64 992.2)" list(-2187.640000 992.200000) nil)@@@list("sky_zheng" "2013/09/13 10:58:16" nil "RDD_704_PC" "g1t-oxygen.10")@@@list("andy_lien" "2013/09/13 12:15:57" nil "ANDY_LIEN-PC" "g1t-oxygen.10") | list("[Spacing] SOLDERMASK_BOTTOM" "25.Pad Soldermask to Pad Soldermask" "6.7 MIL [SOLDERMASK_SPACING]" "0 MIL" "6.70 MIL" "DRC ERROR CLASS/SOLDERMASK_BOTTOM" "[SmdPin] 85_MDSI_C_DP_0 (<uTiL>cId826<uTiL>.2) (-2189.61 965.83)" "[SmdPin] 85_MDSI_C_DP_0 (<uTiL>cId230<uTiL>.2) (-2187.64 967.8)" list(-2187.640000 967.800000) nil)@@@list("sky_zheng" "2013/09/13 10:58:20" nil "RDD_704_PC" "g1t-oxygen.10")@@@list("andy_lien" "2013/09/13 12:15:59" nil "ANDY_LIEN-PC" "g1t-oxygen.10") | list("[Spacing] SOLDERMASK_BOTTOM" "26.Pad Soldermask to Pad Soldermask" "6.7 MIL [SOLDERMASK_SPACING]" "0 MIL" "6.70 MIL" "DRC ERROR CLASS/SOLDERMASK_BOTTOM" "[SmdPin] 85_MDSI_C_DN_0 (<uTiL>cId826<uTiL>.3) (-2189.61 944.17)" "[SmdPin] 85_MDSI_C_DN_0 (<uTiL>cId230<uTiL>.4) (-2187.64 942.2)" list(-2187.640000 942.200000) nil)@@@list("sky_zheng" "2013/09/13 10:58:20" nil "RDD_704_PC" "g1t-oxygen.10")@@@list("andy_lien" "2013/09/13 12:15:59" nil "ANDY_LIEN-PC" "g1t-oxygen.10") | list("[Spacing] SOLDERMASK_BOTTOM" "34.Pad Soldermask to Pad Soldermask" "6.7 MIL [SOLDERMASK_SPACING]" "0 MIL" "6.70 MIL" "DRC ERROR CLASS/SOLDERMASK_BOTTOM" "[SmdPin] 85_MDSI_DP_3 (<uTiL>cId1668<uTiL>.1) (-2140.39 1165.83)" "[SmdPin] 85_MDSI_DP_3 (<uTiL>cId1635<uTiL>.1) (-2142.36 1167.8)" list(-2142.360000 1167.800000) nil)@@@list("sky_zheng" "2013/09/13 10:58:33" nil "RDD_704_PC" "g1t-oxygen.10")@@@list("andy_lien" "2013/09/13 12:16:02" nil "ANDY_LIEN-PC" "g1t-oxygen.10") | list("[Spacing] SOLDERMASK_BOTTOM" "36.Pad Soldermask to Pad Soldermask" "6.7 MIL [SOLDERMASK_SPACING]" "0 MIL" "6.70 MIL" "DRC ERROR CLASS/SOLDERMASK_BOTTOM" "[SmdPin] 85_MDSI_DN_3 (<uTiL>cId1668<uTiL>.4) (-2140.39 1144.17)" "[SmdPin] 85_MDSI_DN_3 (<uTiL>cId1635<uTiL>.3) (-2142.36 1142.2)" list(-2142.360000 1142.200000) nil)@@@list("sky_zheng" "2013/09/13 10:58:35" nil "RDD_704_PC" "g1t-oxygen.10")@@@list("andy_lien" "2013/09/13 12:16:02" nil "ANDY_LIEN-PC" "g1t-oxygen.10") | list("[Spacing] SOLDERMASK_BOTTOM" "38.Pad Soldermask to Pad Soldermask" "6.7 MIL [SOLDERMASK_SPACING]" "0 MIL" "6.70 MIL" "DRC ERROR CLASS/SOLDERMASK_BOTTOM" "[SmdPin] 85_MDSI_DP_2 (<uTiL>cId1669<uTiL>.1) (-2140.39 1115.83)" "[SmdPin] 85_MDSI_DP_2 (<uTiL>cId1636<uTiL>.1) (-2142.36 1117.8)" list(-2142.360000 1117.800000) nil)@@@list("sky_zheng" "2013/09/13 10:58:38" nil "RDD_704_PC" "g1t-oxygen.10")@@@list("andy_lien" "2013/09/13 12:16:05" nil "ANDY_LIEN-PC" "g1t-oxygen.10") | list("[Spacing] SOLDERMASK_BOTTOM" "40.Pad Soldermask to Pad Soldermask" "6.7 MIL [SOLDERMASK_SPACING]" "0 MIL" "6.70 MIL" "DRC ERROR CLASS/SOLDERMASK_BOTTOM" "[SmdPin] 85_MDSI_DN_2 (<uTiL>cId1669<uTiL>.4) (-2140.39 1094.17)" "[SmdPin] 85_MDSI_DN_2 (<uTiL>cId1636<uTiL>.3) (-2142.36 1092.2)" list(-2142.360000 1092.200000) nil)@@@list("sky_zheng" "2013/09/13 10:58:39" nil "RDD_704_PC" "g1t-oxygen.10")@@@list("andy_lien" "2013/09/13 12:16:06" nil "ANDY_LIEN-PC" "g1t-oxygen.10") | list("[Spacing] SOLDERMASK_BOTTOM" "30.Pad Soldermask to Pad Soldermask" "6.7 MIL [SOLDERMASK_SPACING]" "0 MIL" "6.70 MIL" "DRC ERROR CLASS/SOLDERMASK_BOTTOM" "[SmdPin] 85_MDSI_CLK_DP (<uTiL>cId827<uTiL>.1) (-2140.39 1065.83)" "[SmdPin] 85_MDSI_CLK_DP (<uTiL>cId231<uTiL>.1) (-2142.36 1067.8)" list(-2142.360000 1067.800000) nil)@@@list("sky_zheng" "2013/09/13 10:58:29" nil "RDD_704_PC" "g1t-oxygen.10")@@@list("andy_lien" "2013/09/13 12:16:00" nil "ANDY_LIEN-PC" "g1t-oxygen.10") | list("[Spacing] SOLDERMASK_BOTTOM" "32.Pad Soldermask to Pad Soldermask" "6.7 MIL [SOLDERMASK_SPACING]" "0 MIL" "6.70 MIL" "DRC ERROR CLASS/SOLDERMASK_BOTTOM" "[SmdPin] 85_MDSI_CLK_DN (<uTiL>cId827<uTiL>.4) (-2140.39 1044.17)" "[SmdPin] 85_MDSI_CLK_DN (<uTiL>cId231<uTiL>.3) (-2142.36 1042.2)" list(-2142.360000 1042.200000) nil)@@@list("sky_zheng" "2013/09/13 10:58:30" nil "RDD_704_PC" "g1t-oxygen.10")@@@list("andy_lien" "2013/09/13 12:16:01" nil "ANDY_LIEN-PC" "g1t-oxygen.10") | list("[Spacing] SOLDERMASK_BOTTOM" "22.Pad Soldermask to Pad Soldermask" "6.7 MIL [SOLDERMASK_SPACING]" "0 MIL" "6.70 MIL" "DRC ERROR CLASS/SOLDERMASK_BOTTOM" "[SmdPin] 85_MDSI_DP_1 (<uTiL>cId825<uTiL>.1) (-2140.39 1015.83)" "[SmdPin] 85_MDSI_DP_1 (<uTiL>cId229<uTiL>.1) (-2142.36 1017.8)" list(-2142.360000 1017.800000) nil)@@@list("sky_zheng" "2013/09/13 10:58:18" nil "RDD_704_PC" "g1t-oxygen.10")@@@list("andy_lien" "2013/09/13 12:15:58" nil "ANDY_LIEN-PC" "g1t-oxygen.10") | list("[Spacing] SOLDERMASK_BOTTOM" "24.Pad Soldermask to Pad Soldermask" "6.7 MIL [SOLDERMASK_SPACING]" "0 MIL" "6.70 MIL" "DRC ERROR CLASS/SOLDERMASK_BOTTOM" "[SmdPin] 85_MDSI_DN_1 (<uTiL>cId825<uTiL>.4) (-2140.39 994.17)" "[SmdPin] 85_MDSI_DN_1 (<uTiL>cId229<uTiL>.3) (-2142.36 992.2)" list(-2142.360000 992.200000) nil)@@@list("sky_zheng" "2013/09/13 10:58:19" nil "RDD_704_PC" "g1t-oxygen.10")@@@list("andy_lien" "2013/09/13 12:15:58" nil "ANDY_LIEN-PC" "g1t-oxygen.10") | list("[Spacing] SOLDERMASK_BOTTOM" "27.Pad Soldermask to Pad Soldermask" "6.7 MIL [SOLDERMASK_SPACING]" "0 MIL" "6.70 MIL" "DRC ERROR CLASS/SOLDERMASK_BOTTOM" "[SmdPin] 85_MDSI_DP_0 (<uTiL>cId826<uTiL>.1) (-2140.39 965.83)" "[SmdPin] 85_MDSI_DP_0 (<uTiL>cId230<uTiL>.1) (-2142.36 967.8)" list(-2142.360000 967.800000) nil)@@@list("sky_zheng" "2013/09/13 10:58:21" nil "RDD_704_PC" "g1t-oxygen.10")@@@list("andy_lien" "2013/09/13 12:15:59" nil "ANDY_LIEN-PC" "g1t-oxygen.10") | list("[Spacing] SOLDERMASK_BOTTOM" "28.Pad Soldermask to Pad Soldermask" "6.7 MIL [SOLDERMASK_SPACING]" "0 MIL" "6.70 MIL" "DRC ERROR CLASS/SOLDERMASK_BOTTOM" "[SmdPin] 85_MDSI_DN_0 (<uTiL>cId826<uTiL>.4) (-2140.39 944.17)" "[SmdPin] 85_MDSI_DN_0 (<uTiL>cId230<uTiL>.3) (-2142.36 942.2)" list(-2142.360000 942.200000) nil)@@@list("sky_zheng" "2013/09/13 10:58:22" nil "RDD_704_PC" "g1t-oxygen.10")@@@list("andy_lien" "2013/09/13 12:16:00" nil "ANDY_LIEN-PC" "g1t-oxygen.10") | list("[Spacing] SOLDERMASK_BOTTOM" "46.Pad Soldermask to Pad Soldermask" "6.7 MIL [SOLDERMASK_SPACING]" "5.71 MIL" "0.99 MIL" "DRC ERROR CLASS/SOLDERMASK_BOTTOM" "[SmdPin] GND (<uTiL>cId2556<uTiL>.6) (-560.09 166.5)" "[SmdPin] +VSPI_R (<uTiL>cId2556<uTiL>.5) (-577.8 166.5)" list(-577.800000 166.500000) nil)@@@list("sky_zheng" "2013/09/13 10:58:46" nil "RDD_704_PC" "g1t-oxygen.10")@@@list("andy_lien" "2013/09/13 12:16:44" nil "ANDY_LIEN-PC" "g1t-oxygen.10") | list("[Spacing] SOLDERMASK_BOTTOM" "44.Pad Soldermask to Pad Soldermask" "6.7 MIL [SOLDERMASK_SPACING]" "5.71 MIL" "0.99 MIL" "DRC ERROR CLASS/SOLDERMASK_BOTTOM" "[SmdPin] PROG_SPI_IO3 (<uTiL>cId2556<uTiL>.3) (-560.09 103.5)" "[SmdPin] +VSPI_PROG (<uTiL>cId2556<uTiL>.4) (-577.8 103.5)" list(-577.800000 103.500000) nil)@@@list("sky_zheng" "2013/09/13 10:58:43" nil "RDD_704_PC" "g1t-oxygen.10")@@@list("andy_lien" "2013/09/13 12:16:42" nil "ANDY_LIEN-PC" "g1t-oxygen.10") | list("[Spacing] SOLDERMASK_BOTTOM" "43.Pad Soldermask to Pad Soldermask" "6.7 MIL [SOLDERMASK_SPACING]" "5.72 MIL" "0.98 MIL" "DRC ERROR CLASS/SOLDERMASK_BOTTOM" "[SmdPin] N56674876 (<uTiL>cId2556<uTiL>.7) (-542.37 166.5)" "[SmdPin] GND (<uTiL>cId2556<uTiL>.6) (-560.09 166.5)" list(-560.090000 166.500000) nil)@@@list("sky_zheng" "2013/09/13 10:58:41" nil "RDD_704_PC" "g1t-oxygen.10")@@@list("andy_lien" "2013/09/13 12:16:42" nil "ANDY_LIEN-PC" "g1t-oxygen.10") | list("[Spacing] SOLDERMASK_BOTTOM" "41.Pad Soldermask to Pad Soldermask" "6.7 MIL [SOLDERMASK_SPACING]" "5.72 MIL" "0.98 MIL" "DRC ERROR CLASS/SOLDERMASK_BOTTOM" "[SmdPin] N56674880 (<uTiL>cId2556<uTiL>.2) (-542.37 103.5)" "[SmdPin] PROG_SPI_IO3 (<uTiL>cId2556<uTiL>.3) (-560.09 103.5)" list(-560.090000 103.500000) nil)@@@list("sky_zheng" "2013/09/13 10:58:40" nil "RDD_704_PC" "g1t-oxygen.10")@@@list("andy_lien" "2013/09/13 12:16:06" nil "ANDY_LIEN-PC" "g1t-oxygen.10") | list("[Spacing] SOLDERMASK_BOTTOM" "45.Pad Soldermask to Pad Soldermask" "6.7 MIL [SOLDERMASK_SPACING]" "5.71 MIL" "0.99 MIL" "DRC ERROR CLASS/SOLDERMASK_BOTTOM" "[SmdPin] N56674876 (<uTiL>cId2556<uTiL>.7) (-542.37 166.5)" "[SmdPin] +VSPI_R (<uTiL>cId2556<uTiL>.8) (-524.66 166.5)" list(-524.660000 166.500000) nil)@@@list("sky_zheng" "2013/09/13 10:58:44" nil "RDD_704_PC" "g1t-oxygen.10")@@@list("andy_lien" "2013/09/13 12:16:43" nil "ANDY_LIEN-PC" "g1t-oxygen.10") | list("[Spacing] SOLDERMASK_BOTTOM" "42.Pad Soldermask to Pad Soldermask" "6.7 MIL [SOLDERMASK_SPACING]" "5.71 MIL" "0.99 MIL" "DRC ERROR CLASS/SOLDERMASK_BOTTOM" "[SmdPin] N56674880 (<uTiL>cId2556<uTiL>.2) (-542.37 103.5)" "[SmdPin] +V1P8A (<uTiL>cId2556<uTiL>.1) (-524.66 105.5)" list(-524.660000 105.500000) nil)@@@list("sky_zheng" "2013/09/13 10:58:42" nil "RDD_704_PC" "g1t-oxygen.10")@@@list("andy_lien" "2013/09/13 12:16:41" nil "ANDY_LIEN-PC" "g1t-oxygen.10") | list("[Spacing] SOLDERMASK_BOTTOM" "7.Pad Soldermask to Pad Soldermask" "6.7 MIL [SOLDERMASK_SPACING]" "0 MIL" "6.70 MIL" "DRC ERROR CLASS/SOLDERMASK_BOTTOM" "[SmdPin] 85_MCSI_2_CLK_DP (<uTiL>cId875<uTiL>.4) (-364.61 1288.83)" "[SmdPin] 85_MCSI_2_CLK_DP (<uTiL>cId2109<uTiL>.3) (-362.64 1290.8)" list(-362.640000 1290.800000) nil)@@@list("sky_zheng" "2013/09/13 10:57:55" nil "RDD_704_PC" "g1t-oxygen.10")@@@list("andy_lien" "2013/09/13 12:15:51" nil "ANDY_LIEN-PC" "g1t-oxygen.10") | list("[Spacing] SOLDERMASK_BOTTOM" "8.Pad Soldermask to Pad Soldermask" "6.7 MIL [SOLDERMASK_SPACING]" "0 MIL" "6.70 MIL" "DRC ERROR CLASS/SOLDERMASK_BOTTOM" "[SmdPin] 85_MCSI_2_CLK_DN (<uTiL>cId875<uTiL>.1) (-364.61 1267.17)" "[SmdPin] 85_MCSI_2_CLK_DN (<uTiL>cId2109<uTiL>.1) (-362.64 1265.2)" list(-362.640000 1265.200000) nil)@@@list("sky_zheng" "2013/09/13 10:57:53" nil "RDD_704_PC" "g1t-oxygen.10")@@@list("andy_lien" "2013/09/13 12:15:52" nil "ANDY_LIEN-PC" "g1t-oxygen.10") | list("[Spacing] SOLDERMASK_BOTTOM" "4.Pad Soldermask to Pad Soldermask" "6.7 MIL [SOLDERMASK_SPACING]" "0 MIL" "6.70 MIL" "DRC ERROR CLASS/SOLDERMASK_BOTTOM" "[SmdPin] 85_MCSI_2_DATA_DP (<uTiL>cId876<uTiL>.4) (-364.61 1239.83)" "[SmdPin] 85_MCSI_2_DATA_DP (<uTiL>cId2108<uTiL>.3) (-362.64 1241.8)" list(-362.640000 1241.800000) nil)@@@list("sky_zheng" "2013/09/13 10:57:51" nil "RDD_704_PC" "g1t-oxygen.10")@@@list("andy_lien" "2013/09/13 12:15:49" nil "ANDY_LIEN-PC" "g1t-oxygen.10") | list("[Spacing] SOLDERMASK_BOTTOM" "3.Pad Soldermask to Pad Soldermask" "6.7 MIL [SOLDERMASK_SPACING]" "0 MIL" "6.70 MIL" "DRC ERROR CLASS/SOLDERMASK_BOTTOM" "[SmdPin] 85_MCSI_2_DATA_DN (<uTiL>cId876<uTiL>.1) (-364.61 1218.17)" "[SmdPin] 85_MCSI_2_DATA_DN (<uTiL>cId2108<uTiL>.1) (-362.64 1216.2)" list(-362.640000 1216.200000) nil)@@@list("sky_zheng" "2013/09/13 10:57:50" nil "RDD_704_PC" "g1t-oxygen.10")@@@list("andy_lien" "2013/09/13 12:15:49" nil "ANDY_LIEN-PC" "g1t-oxygen.10") | list("[Spacing] SOLDERMASK_BOTTOM" "6.Pad Soldermask to Pad Soldermask" "6.7 MIL [SOLDERMASK_SPACING]" "0 MIL" "6.70 MIL" "DRC ERROR CLASS/SOLDERMASK_BOTTOM" "[SmdPin] 85_MCSI_2_CLK_DP_CON (<uTiL>cId875<uTiL>.3) (-315.39 1288.83)" "[SmdPin] 85_MCSI_2_CLK_DP_CON (<uTiL>cId2109<uTiL>.4) (-317.36 1290.8)" list(-317.360000 1290.800000) nil)@@@list("sky_zheng" "2013/09/13 10:57:52" nil "RDD_704_PC" "g1t-oxygen.10")@@@list("andy_lien" "2013/09/13 12:15:50" nil "ANDY_LIEN-PC" "g1t-oxygen.10") | list("[Spacing] SOLDERMASK_BOTTOM" "5.Pad Soldermask to Pad Soldermask" "6.7 MIL [SOLDERMASK_SPACING]" "0 MIL" "6.70 MIL" "DRC ERROR CLASS/SOLDERMASK_BOTTOM" "[SmdPin] 85_MCSI_2_CLK_DN_CON (<uTiL>cId875<uTiL>.2) (-315.39 1267.17)" "[SmdPin] 85_MCSI_2_CLK_DN_CON (<uTiL>cId2109<uTiL>.2) (-317.36 1265.2)" list(-317.360000 1265.200000) nil)@@@list("sky_zheng" "2013/09/13 10:57:51" nil "RDD_704_PC" "g1t-oxygen.10")@@@list("andy_lien" "2013/09/13 12:15:50" nil "ANDY_LIEN-PC" "g1t-oxygen.10") | list("[Spacing] SOLDERMASK_BOTTOM" "2.Pad Soldermask to Pad Soldermask" "6.7 MIL [SOLDERMASK_SPACING]" "0 MIL" "6.70 MIL" "DRC ERROR CLASS/SOLDERMASK_BOTTOM" "[SmdPin] 85_MCSI_2_DATA_DP_CON (<uTiL>cId876<uTiL>.3) (-315.39 1239.83)" "[SmdPin] 85_MCSI_2_DATA_DP_CON (<uTiL>cId2108<uTiL>.4) (-317.36 1241.8)" list(-317.360000 1241.800000) nil)@@@list("sky_zheng" "2013/09/13 10:57:49" nil "RDD_704_PC" "g1t-oxygen.10")@@@list("andy_lien" "2013/09/13 12:15:48" nil "ANDY_LIEN-PC" "g1t-oxygen.10") | list("[Spacing] SOLDERMASK_BOTTOM" "1.Pad Soldermask to Pad Soldermask" "6.7 MIL [SOLDERMASK_SPACING]" "0 MIL" "6.70 MIL" "DRC ERROR CLASS/SOLDERMASK_BOTTOM" "[SmdPin] 85_MCSI_2_DATA_DN_CON (<uTiL>cId876<uTiL>.2) (-315.39 1218.17)" "[SmdPin] 85_MCSI_2_DATA_DN_CON (<uTiL>cId2108<uTiL>.2) (-317.36 1216.2)" list(-317.360000 1216.200000) nil)@@@list("sky_zheng" "2013/09/13 10:57:48" nil "RDD_704_PC" "g1t-oxygen.10")@@@list("andy_lien" "2013/09/13 12:15:47" nil "ANDY_LIEN-PC" "g1t-oxygen.10") | list("[Spacing] SOLDERMASK_BOTTOM" "16.Pad Soldermask to Pad Soldermask" "6.7 MIL [SOLDERMASK_SPACING]" "0 MIL" "6.70 MIL" "DRC ERROR CLASS/SOLDERMASK_BOTTOM" "[SmdPin] 85_MCSI_1_DATA_DP_CON (<uTiL>cId874<uTiL>.3) (1999.17 1249.61)" "[SmdPin] 85_MCSI_1_DATA_DP_CON (<uTiL>cId225<uTiL>.4) (1997.2 1247.64)" list(1997.200000 1247.640000) nil)@@@list("sky_zheng" "2013/09/13 10:58:07" nil "RDD_704_PC" "g1t-oxygen.10")@@@list("andy_lien" "2013/09/13 12:15:56" nil "ANDY_LIEN-PC" "g1t-oxygen.10") | list("[Spacing] SOLDERMASK_BOTTOM" "15.Pad Soldermask to Pad Soldermask" "6.7 MIL [SOLDERMASK_SPACING]" "0 MIL" "6.70 MIL" "DRC ERROR CLASS/SOLDERMASK_BOTTOM" "[SmdPin] 85_MCSI_1_DATA_DP (<uTiL>cId874<uTiL>.4) (1999.17 1200.39)" "[SmdPin] 85_MCSI_1_DATA_DP (<uTiL>cId225<uTiL>.3) (1997.2 1202.36)" list(1997.200000 1202.360000) nil)@@@list("sky_zheng" "2013/09/13 10:58:10" nil "RDD_704_PC" "g1t-oxygen.10")@@@list("andy_lien" "2013/09/13 12:15:55" nil "ANDY_LIEN-PC" "g1t-oxygen.10") | list("[Spacing] SOLDERMASK_BOTTOM" "13.Pad Soldermask to Pad Soldermask" "6.7 MIL [SOLDERMASK_SPACING]" "0 MIL" "6.70 MIL" "DRC ERROR CLASS/SOLDERMASK_BOTTOM" "[SmdPin] 85_MCSI_1_DATA_DN_CON (<uTiL>cId874<uTiL>.2) (2020.83 1249.61)" "[SmdPin] 85_MCSI_1_DATA_DN_CON (<uTiL>cId225<uTiL>.2) (2022.8 1247.64)" list(2022.800000 1247.640000) nil)@@@list("sky_zheng" "2013/09/13 10:58:05" nil "RDD_704_PC" "g1t-oxygen.10")@@@list("andy_lien" "2013/09/13 12:15:54" nil "ANDY_LIEN-PC" "g1t-oxygen.10") | list("[Spacing] SOLDERMASK_BOTTOM" "14.Pad Soldermask to Pad Soldermask" "6.7 MIL [SOLDERMASK_SPACING]" "0 MIL" "6.70 MIL" "DRC ERROR CLASS/SOLDERMASK_BOTTOM" "[SmdPin] 85_MCSI_1_DATA_DN (<uTiL>cId874<uTiL>.1) (2020.83 1200.39)" "[SmdPin] 85_MCSI_1_DATA_DN (<uTiL>cId225<uTiL>.1) (2022.8 1202.36)" list(2022.800000 1202.360000) nil)@@@list("sky_zheng" "2013/09/13 10:58:08" nil "RDD_704_PC" "g1t-oxygen.10")@@@list("andy_lien" "2013/09/13 12:15:55" nil "ANDY_LIEN-PC" "g1t-oxygen.10") | list("[Spacing] SOLDERMASK_BOTTOM" "10.Pad Soldermask to Pad Soldermask" "6.7 MIL [SOLDERMASK_SPACING]" "0 MIL" "6.70 MIL" "DRC ERROR CLASS/SOLDERMASK_BOTTOM" "[SmdPin] 85_MCSI_1_CLK_DP_CON (<uTiL>cId2164<uTiL>.3) (2054.17 1249.61)" "[SmdPin] 85_MCSI_1_CLK_DP_CON (<uTiL>cId224<uTiL>.4) (2052.2 1247.64)" list(2052.200000 1247.640000) nil)@@@list("sky_zheng" "2013/09/13 10:58:02" nil "RDD_704_PC" "g1t-oxygen.10")@@@list("andy_lien" "2013/09/13 12:15:53" nil "ANDY_LIEN-PC" "g1t-oxygen.10") | list("[Spacing] SOLDERMASK_BOTTOM" "12.Pad Soldermask to Pad Soldermask" "6.7 MIL [SOLDERMASK_SPACING]" "0 MIL" "6.70 MIL" "DRC ERROR CLASS/SOLDERMASK_BOTTOM" "[SmdPin] 85_MCSI_1_CLK_DP (<uTiL>cId2164<uTiL>.4) (2054.17 1200.39)" "[SmdPin] 85_MCSI_1_CLK_DP (<uTiL>cId224<uTiL>.3) (2052.2 1202.36)" list(2052.200000 1202.360000) nil)@@@list("sky_zheng" "2013/09/13 10:58:04" nil "RDD_704_PC" "g1t-oxygen.10")@@@list("andy_lien" "2013/09/13 12:15:54" nil "ANDY_LIEN-PC" "g1t-oxygen.10") | list("[Spacing] SOLDERMASK_BOTTOM" "9.Pad Soldermask to Pad Soldermask" "6.7 MIL [SOLDERMASK_SPACING]" "0 MIL" "6.70 MIL" "DRC ERROR CLASS/SOLDERMASK_BOTTOM" "[SmdPin] 85_MCSI_1_CLK_DN_CON (<uTiL>cId2164<uTiL>.2) (2075.83 1249.61)" "[SmdPin] 85_MCSI_1_CLK_DN_CON (<uTiL>cId224<uTiL>.2) (2077.8 1247.64)" list(2077.800000 1247.640000) nil)@@@list("sky_zheng" "2013/09/13 10:57:56" nil "RDD_704_PC" "g1t-oxygen.10")@@@list("andy_lien" "2013/09/13 12:15:53" nil "ANDY_LIEN-PC" "g1t-oxygen.10") | list("[Spacing] SOLDERMASK_BOTTOM" "11.Pad Soldermask to Pad Soldermask" "6.7 MIL [SOLDERMASK_SPACING]" "0 MIL" "6.70 MIL" "DRC ERROR CLASS/SOLDERMASK_BOTTOM" "[SmdPin] 85_MCSI_1_CLK_DN (<uTiL>cId2164<uTiL>.1) (2075.83 1200.39)" "[SmdPin] 85_MCSI_1_CLK_DN (<uTiL>cId224<uTiL>.1) (2077.8 1202.36)" list(2077.800000 1202.360000) nil)@@@list("sky_zheng" "2013/09/13 10:58:03" nil "RDD_704_PC" "g1t-oxygen.10")@@@list("andy_lien" "2013/09/13 12:15:54" nil "ANDY_LIEN-PC" "g1t-oxygen.10") | list("[Spacing] SOLDERMASK_BOTTOM" "20.Pad Soldermask to Pad Soldermask" "6.7 MIL [SOLDERMASK_SPACING]" "0 MIL" "6.70 MIL" "DRC ERROR CLASS/SOLDERMASK_BOTTOM" "[SmdPin] 85_MCSI_1_DATA2_DP_CON (<uTiL>cId3124<uTiL>.3) (2109.17 1249.61)" "[SmdPin] 85_MCSI_1_DATA2_DP_CON (<uTiL>cId3123<uTiL>.4) (2107.2 1247.64)" list(2107.200000 1247.640000) nil)@@@list("sky_zheng" "2013/09/13 10:58:12" nil "RDD_704_PC" "g1t-oxygen.10")@@@list("andy_lien" "2013/09/13 12:15:57" nil "ANDY_LIEN-PC" "g1t-oxygen.10") | list("[Spacing] SOLDERMASK_BOTTOM" "19.Pad Soldermask to Pad Soldermask" "6.7 MIL [SOLDERMASK_SPACING]" "0 MIL" "6.70 MIL" "DRC ERROR CLASS/SOLDERMASK_BOTTOM" "[SmdPin] 85_MCSI_1_DATA2_DP (<uTiL>cId3124<uTiL>.4) (2109.17 1200.39)" "[SmdPin] 85_MCSI_1_DATA2_DP (<uTiL>cId3123<uTiL>.3) (2107.2 1202.36)" list(2107.200000 1202.360000) nil)@@@list("sky_zheng" "2013/09/13 10:58:15" nil "RDD_704_PC" "g1t-oxygen.10")@@@list("andy_lien" "2013/09/13 12:15:57" nil "ANDY_LIEN-PC" "g1t-oxygen.10") | list("[Spacing] SOLDERMASK_BOTTOM" "17.Pad Soldermask to Pad Soldermask" "6.7 MIL [SOLDERMASK_SPACING]" "0 MIL" "6.70 MIL" "DRC ERROR CLASS/SOLDERMASK_BOTTOM" "[SmdPin] 85_MCSI_1_DATA2_DN_CON (<uTiL>cId3124<uTiL>.2) (2130.83 1249.61)" "[SmdPin] 85_MCSI_1_DATA2_DN_CON (<uTiL>cId3123<uTiL>.2) (2132.8 1247.64)" list(2132.800000 1247.640000) nil)@@@list("sky_zheng" "2013/09/13 10:58:11" nil "RDD_704_PC" "g1t-oxygen.10")@@@list("andy_lien" "2013/09/13 12:15:56" nil "ANDY_LIEN-PC" "g1t-oxygen.10") | list("[Spacing] SOLDERMASK_BOTTOM" "18.Pad Soldermask to Pad Soldermask" "6.7 MIL [SOLDERMASK_SPACING]" "0 MIL" "6.70 MIL" "DRC ERROR CLASS/SOLDERMASK_BOTTOM" "[SmdPin] 85_MCSI_1_DATA2_DN (<uTiL>cId3124<uTiL>.1) (2130.83 1200.39)" "[SmdPin] 85_MCSI_1_DATA2_DN (<uTiL>cId3123<uTiL>.1) (2132.8 1202.36)" list(2132.800000 1202.360000) nil)@@@list("sky_zheng" "2013/09/13 10:58:13" nil "RDD_704_PC" "g1t-oxygen.10")@@@list("andy_lien" "2013/09/13 12:15:56" nil "ANDY_LIEN-PC" "g1t-oxygen.10")
